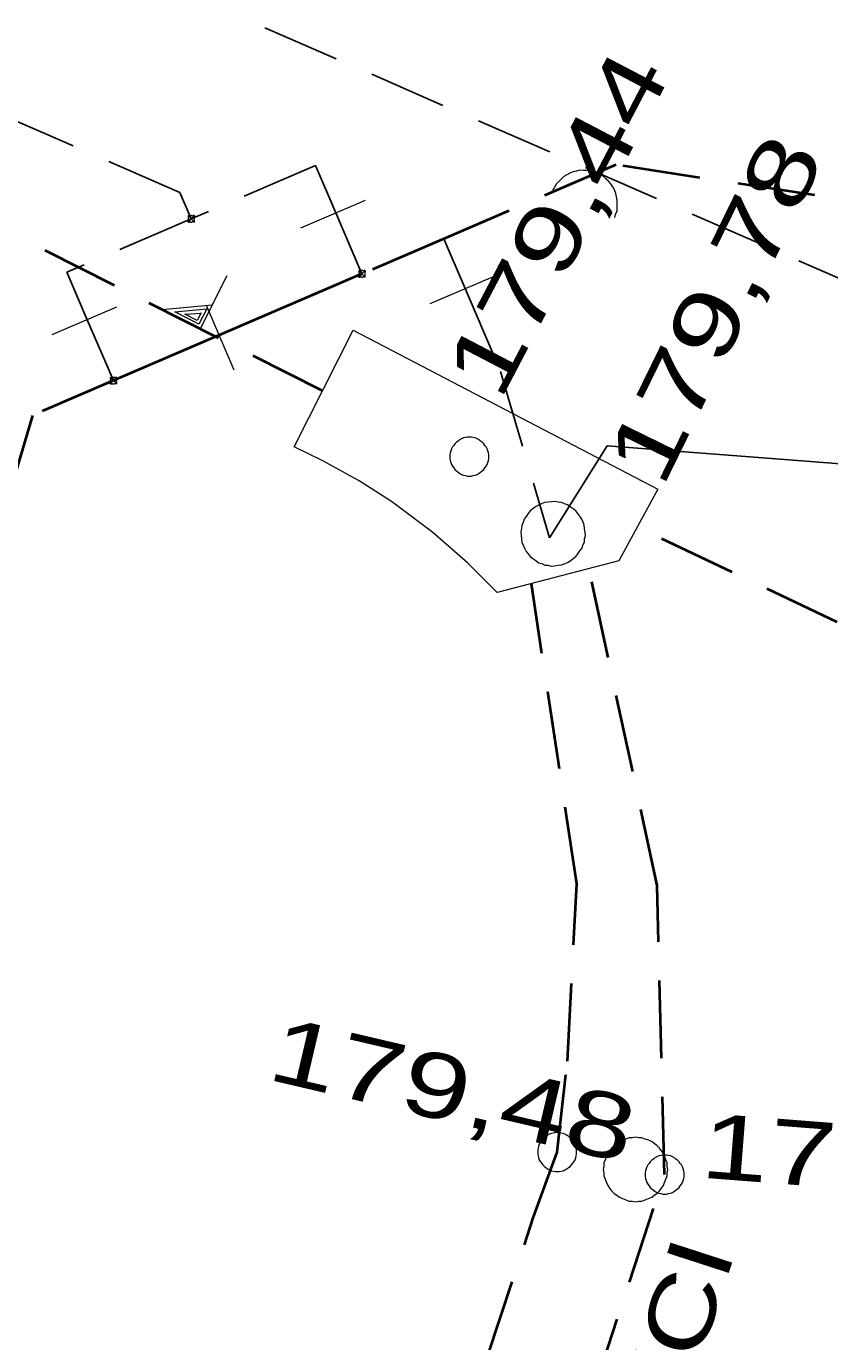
# Model space of a CAD drawing. Extents: x -740851 to -738888, y -1041382 to -1040235.
# Drawn here: x -739019.6 to -739007.19, y -1041347.67 to -1041327.35 of the extents above; entities that cross this region are included whole.
import ezdxf

# ---------------------------------------------------------------- set-up
doc = ezdxf.new("R2010")
doc.units = 0
doc.header["$LTSCALE"] = 0.4
doc.linetypes.add('MEDIUM_DASHED', pattern=[4.5, 3, -1.5])
doc.layers.add('18', color=7, linetype='Continuous', lineweight=13)
doc.layers.add('8', color=7, linetype='Continuous', lineweight=13)

msp = doc.modelspace()

# ---------------------------------------------------------------- linework, layer by layer
at = {"layer": '18', "linetype": 'MEDIUM_DASHED', "lineweight": 40}
msp.add_line((-739014.211, -1041358.725), (-739009.74, -1041345.09), dxfattribs=at)
for points in [[(-739015.025, -1041332.979), (-739045.2, -1041317.71), (-739098.28, -1041294.28)], [(-738957.54, -1041347.45), (-738989.227, -1041342.273), (-738994.634, -1041341.058), (-739000.628, -1041339.172), (-739005.448, -1041337.328), (-739010.163, -1041335.083)], [(-739009.74, -1041345.09), (-739009.855, -1041340.621), (-739010.909, -1041335.728)], [(-739011.4, -1041344.741), (-739011.241, -1041343.336), (-739011.097, -1041340.599), (-739011.799, -1041335.96)], [(-739015.852, -1041358.143), (-739011.77, -1041345.76), (-739011.4, -1041344.741)]]:
    msp.add_lwpolyline(points, dxfattribs=at)
at = {"layer": '18'}
for points in [[(-739016.501, -1041331.2), (-739016.916, -1041332.02), (-739017.501, -1041331.724), (-739016.729, -1041331.65)], [(-739016.813, -1041331.71), (-739016.934, -1041331.949), (-739017.308, -1041331.76), (-739016.81, -1041331.712)], [(-739016.9, -1041331.775), (-739016.96, -1041331.894), (-739017.152, -1041331.797), (-739016.896, -1041331.777)]]:
    msp.add_lwpolyline(points, dxfattribs=at)
for points in [[(-739009.847, -1041334.498), (-739010.447, -1041335.608), (-739012.327, -1041336.098), (-739012.781, -1041335.64), (-739013.321, -1041335.166), (-739013.959, -1041334.69), (-739014.46, -1041334.369), (-739015.019, -1041334.059), (-739015.463, -1041333.845), (-739014.551, -1041332.041)], [(-739012.457, -1041333.996), (-739012.457, -1041333.966), (-739012.463, -1041333.936), (-739012.469, -1041333.906), (-739012.481, -1041333.876), (-739012.499, -1041333.846), (-739012.517, -1041333.822), (-739012.535, -1041333.798), (-739012.559, -1041333.774), (-739012.583, -1041333.756), (-739012.607, -1041333.738), (-739012.637, -1041333.72), (-739012.667, -1041333.708), (-739012.697, -1041333.702), (-739012.727, -1041333.696), (-739012.757, -1041333.696), (-739012.787, -1041333.696), (-739012.817, -1041333.702), (-739012.847, -1041333.708), (-739012.877, -1041333.72), (-739012.907, -1041333.738), (-739012.931, -1041333.756), (-739012.955, -1041333.774), (-739012.979, -1041333.798), (-739012.997, -1041333.822), (-739013.015, -1041333.846), (-739013.033, -1041333.876), (-739013.045, -1041333.906), (-739013.051, -1041333.936), (-739013.057, -1041333.966), (-739013.057, -1041333.996), (-739013.057, -1041334.026), (-739013.051, -1041334.056), (-739013.045, -1041334.086), (-739013.033, -1041334.116), (-739013.015, -1041334.146), (-739012.997, -1041334.17), (-739012.979, -1041334.194), (-739012.955, -1041334.218), (-739012.931, -1041334.236), (-739012.907, -1041334.254), (-739012.877, -1041334.272), (-739012.847, -1041334.284), (-739012.817, -1041334.29), (-739012.787, -1041334.296), (-739012.757, -1041334.296), (-739012.727, -1041334.296), (-739012.697, -1041334.29), (-739012.667, -1041334.284), (-739012.637, -1041334.272), (-739012.607, -1041334.254), (-739012.583, -1041334.236), (-739012.559, -1041334.218), (-739012.535, -1041334.194), (-739012.517, -1041334.17), (-739012.499, -1041334.146), (-739012.481, -1041334.116), (-739012.469, -1041334.086), (-739012.463, -1041334.056), (-739012.457, -1041334.026)], [(-739010.98, -1041335.317), (-739010.977, -1041335.266), (-739010.964, -1041335.218), (-739010.97, -1041335.164), (-739010.976, -1041335.111), (-739010.983, -1041335.057), (-739011.001, -1041335.011), (-739011.02, -1041334.964), (-739011.048, -1041334.915), (-739011.079, -1041334.876), (-739011.11, -1041334.836), (-739011.153, -1041334.804), (-739011.197, -1041334.772), (-739011.24, -1041334.739), (-739011.288, -1041334.726), (-739011.334, -1041334.704), (-739011.385, -1041334.7), (-739011.433, -1041334.687), (-739011.487, -1041334.694), (-739011.54, -1041334.7), (-739011.594, -1041334.707), (-739011.64, -1041334.725), (-739011.687, -1041334.744), (-739011.736, -1041334.772), (-739011.775, -1041334.803), (-739011.815, -1041334.834), (-739011.847, -1041334.877), (-739011.879, -1041334.92), (-739011.912, -1041334.964), (-739011.925, -1041335.012), (-739011.947, -1041335.058), (-739011.951, -1041335.109), (-739011.964, -1041335.157), (-739011.957, -1041335.211), (-739011.951, -1041335.264), (-739011.944, -1041335.318), (-739011.926, -1041335.364), (-739011.907, -1041335.411), (-739011.879, -1041335.46), (-739011.848, -1041335.499), (-739011.817, -1041335.539), (-739011.774, -1041335.571), (-739011.731, -1041335.603), (-739011.687, -1041335.636), (-739011.639, -1041335.649), (-739011.593, -1041335.671), (-739011.542, -1041335.674), (-739011.494, -1041335.687), (-739011.44, -1041335.681), (-739011.387, -1041335.675), (-739011.333, -1041335.668), (-739011.287, -1041335.65), (-739011.24, -1041335.631), (-739011.191, -1041335.603), (-739011.152, -1041335.572), (-739011.112, -1041335.541), (-739011.08, -1041335.498), (-739011.048, -1041335.454), (-739011.015, -1041335.411), (-739011.002, -1041335.363)], [(-739011.1, -1041344.741), (-739011.1, -1041344.711), (-739011.106, -1041344.681), (-739011.112, -1041344.651), (-739011.124, -1041344.621), (-739011.142, -1041344.591), (-739011.16, -1041344.567), (-739011.178, -1041344.543), (-739011.202, -1041344.519), (-739011.226, -1041344.501), (-739011.25, -1041344.483), (-739011.28, -1041344.465), (-739011.31, -1041344.453), (-739011.34, -1041344.447), (-739011.37, -1041344.441), (-739011.4, -1041344.441), (-739011.43, -1041344.441), (-739011.46, -1041344.447), (-739011.49, -1041344.453), (-739011.52, -1041344.465), (-739011.55, -1041344.483), (-739011.574, -1041344.501), (-739011.598, -1041344.519), (-739011.622, -1041344.543), (-739011.64, -1041344.567), (-739011.658, -1041344.591), (-739011.676, -1041344.621), (-739011.688, -1041344.651), (-739011.694, -1041344.681), (-739011.7, -1041344.711), (-739011.7, -1041344.741), (-739011.7, -1041344.771), (-739011.694, -1041344.801), (-739011.688, -1041344.831), (-739011.676, -1041344.861), (-739011.658, -1041344.891), (-739011.64, -1041344.915), (-739011.622, -1041344.939), (-739011.598, -1041344.963), (-739011.574, -1041344.981), (-739011.55, -1041344.999), (-739011.52, -1041345.017), (-739011.49, -1041345.029), (-739011.46, -1041345.035), (-739011.43, -1041345.041), (-739011.4, -1041345.041), (-739011.37, -1041345.041), (-739011.34, -1041345.035), (-739011.31, -1041345.029), (-739011.28, -1041345.017), (-739011.25, -1041344.999), (-739011.226, -1041344.981), (-739011.202, -1041344.963), (-739011.178, -1041344.939), (-739011.16, -1041344.915), (-739011.142, -1041344.891), (-739011.124, -1041344.861), (-739011.112, -1041344.831), (-739011.106, -1041344.801), (-739011.1, -1041344.771)], [(-739009.69, -1041345.01), (-739009.7, -1041344.96), (-739009.7, -1041344.91), (-739009.72, -1041344.86), (-739009.74, -1041344.81), (-739009.76, -1041344.76), (-739009.79, -1041344.72), (-739009.82, -1041344.68), (-739009.86, -1041344.64), (-739009.9, -1041344.61), (-739009.94, -1041344.58), (-739009.99, -1041344.56), (-739010.04, -1041344.54), (-739010.09, -1041344.52), (-739010.14, -1041344.52), (-739010.19, -1041344.51), (-739010.24, -1041344.52), (-739010.29, -1041344.52), (-739010.34, -1041344.54), (-739010.39, -1041344.56), (-739010.44, -1041344.58), (-739010.48, -1041344.61), (-739010.52, -1041344.64), (-739010.56, -1041344.68), (-739010.59, -1041344.72), (-739010.62, -1041344.76), (-739010.64, -1041344.81), (-739010.66, -1041344.86), (-739010.68, -1041344.91), (-739010.68, -1041344.96), (-739010.69, -1041345.01), (-739010.68, -1041345.06), (-739010.68, -1041345.11), (-739010.66, -1041345.16), (-739010.64, -1041345.21), (-739010.62, -1041345.26), (-739010.59, -1041345.3), (-739010.56, -1041345.34), (-739010.52, -1041345.38), (-739010.48, -1041345.41), (-739010.44, -1041345.44), (-739010.39, -1041345.46), (-739010.34, -1041345.48), (-739010.29, -1041345.5), (-739010.24, -1041345.5), (-739010.19, -1041345.51), (-739010.14, -1041345.5), (-739010.09, -1041345.5), (-739010.04, -1041345.48), (-739009.99, -1041345.46), (-739009.94, -1041345.44), (-739009.9, -1041345.41), (-739009.86, -1041345.38), (-739009.82, -1041345.34), (-739009.79, -1041345.3), (-739009.76, -1041345.26), (-739009.74, -1041345.21), (-739009.72, -1041345.16), (-739009.7, -1041345.11), (-739009.7, -1041345.06)], [(-739009.44, -1041345.09), (-739009.44, -1041345.06), (-739009.446, -1041345.03), (-739009.452, -1041345), (-739009.464, -1041344.97), (-739009.482, -1041344.94), (-739009.5, -1041344.916), (-739009.518, -1041344.892), (-739009.542, -1041344.868), (-739009.566, -1041344.85), (-739009.59, -1041344.832), (-739009.62, -1041344.814), (-739009.65, -1041344.802), (-739009.68, -1041344.796), (-739009.71, -1041344.79), (-739009.74, -1041344.79), (-739009.77, -1041344.79), (-739009.8, -1041344.796), (-739009.83, -1041344.802), (-739009.86, -1041344.814), (-739009.89, -1041344.832), (-739009.914, -1041344.85), (-739009.938, -1041344.868), (-739009.962, -1041344.892), (-739009.98, -1041344.916), (-739009.998, -1041344.94), (-739010.016, -1041344.97), (-739010.028, -1041345), (-739010.034, -1041345.03), (-739010.04, -1041345.06), (-739010.04, -1041345.09), (-739010.04, -1041345.12), (-739010.034, -1041345.15), (-739010.028, -1041345.18), (-739010.016, -1041345.21), (-739009.998, -1041345.24), (-739009.98, -1041345.264), (-739009.962, -1041345.288), (-739009.938, -1041345.312), (-739009.914, -1041345.33), (-739009.89, -1041345.348), (-739009.86, -1041345.366), (-739009.83, -1041345.378), (-739009.8, -1041345.384), (-739009.77, -1041345.39), (-739009.74, -1041345.39), (-739009.71, -1041345.39), (-739009.68, -1041345.384), (-739009.65, -1041345.378), (-739009.62, -1041345.366), (-739009.59, -1041345.348), (-739009.566, -1041345.33), (-739009.542, -1041345.312), (-739009.518, -1041345.288), (-739009.5, -1041345.264), (-739009.482, -1041345.24), (-739009.464, -1041345.21), (-739009.452, -1041345.18), (-739009.446, -1041345.15), (-739009.44, -1041345.12)]]:
    msp.add_lwpolyline(points, close=True, dxfattribs=at)
at = {"layer": '8'}
for p, q in [((-739015.36, -1041330.462), (-739014.36, -1041330.032)), ((-739017.101, -1041330.372), (-739017.001, -1041330.272)), ((-739017.101, -1041330.272), (-739017.001, -1041330.372)), ((-739017.101, -1041330.272), (-739017.101, -1041330.292)), ((-739017.101, -1041330.272), (-739017.081, -1041330.272)), ((-739017.001, -1041330.272), (-739017.021, -1041330.272)), ((-739017.001, -1041330.272), (-739017.001, -1041330.292)), ((-739017.101, -1041330.372), (-739017.101, -1041330.352)), ((-739017.101, -1041330.372), (-739017.081, -1041330.372)), ((-739017.001, -1041330.372), (-739017.021, -1041330.372)), ((-739017.001, -1041330.372), (-739017.001, -1041330.352)), ((-739014.464, -1041331.221), (-739014.364, -1041331.121)), ((-739014.464, -1041331.121), (-739014.364, -1041331.221)), ((-739014.464, -1041331.121), (-739014.464, -1041331.141)), ((-739014.464, -1041331.121), (-739014.444, -1041331.121)), ((-739014.364, -1041331.121), (-739014.384, -1041331.121)), ((-739014.364, -1041331.121), (-739014.364, -1041331.141)), ((-739014.464, -1041331.221), (-739014.464, -1041331.201)), ((-739014.464, -1041331.221), (-739014.444, -1041331.221)), ((-739014.364, -1041331.221), (-739014.384, -1041331.221)), ((-739014.364, -1041331.221), (-739014.364, -1041331.201)), ((-739013.36, -1041331.63), (-739012.36, -1041331.204)), ((-739019.2, -1041332.11), (-739018.2, -1041331.684)), ((-739016.388, -1041332.66), (-739016.818, -1041331.66)), ((-739018.304, -1041332.871), (-739018.204, -1041332.771)), ((-739018.304, -1041332.771), (-739018.204, -1041332.871)), ((-739018.304, -1041332.771), (-739018.304, -1041332.791)), ((-739018.304, -1041332.771), (-739018.284, -1041332.771)), ((-739018.204, -1041332.771), (-739018.224, -1041332.771)), ((-739018.204, -1041332.771), (-739018.204, -1041332.791)), ((-739018.304, -1041332.871), (-739018.304, -1041332.851)), ((-739018.304, -1041332.871), (-739018.284, -1041332.871)), ((-739018.204, -1041332.871), (-739018.224, -1041332.871)), ((-739018.204, -1041332.871), (-739018.204, -1041332.851))]:
    msp.add_line(p, q, dxfattribs=at)
at = {"layer": '8', "lineweight": 25}
for p, q in [((-739014.415, -1041331.172), (-739014.82, -1041330.23)), ((-739013.151, -1041330.629), (-739012.82, -1041331.4)), ((-739018.66, -1041331.88), (-739018.255, -1041332.822))]:
    msp.add_line(p, q, dxfattribs=at)
at = {"layer": '8', "lineweight": 40}
for p, q in [((-739014.415, -1041331.172), (-739016.62, -1041332.12)), ((-739016.62, -1041332.12), (-739018.255, -1041332.822))]:
    msp.add_line(p, q, dxfattribs=at)
at = {"layer": '8', "linetype": 'MEDIUM_DASHED', "lineweight": 40}
for points in [[(-739035.327, -1040869.176), (-739031.896, -1040886.019), (-739019.793, -1040911.158), (-738971.377, -1041006.096), (-738926.048, -1041090.986), (-738916.972, -1041110.384), (-738894.08, -1041157.618), (-738888.006, -1041177.327), (-738893.192, -1041219.807), (-738897.568, -1041245.006), (-738897.033, -1041287.959), (-738895.284, -1041302.914), (-738892.075, -1041339.057), (-738904.789, -1041346.08), (-738934.47, -1041341.14), (-739010.494, -1041329.487), (-739013.151, -1041330.629), (-739014.415, -1041331.172)], [(-739018.255, -1041332.822), (-739019.505, -1041333.359), (-739022.37, -1041343.05), (-739027.082, -1041357.662)]]:
    msp.add_lwpolyline(points, dxfattribs=at)
at = {"layer": '8', "linetype": 'MEDIUM_DASHED', "lineweight": 25}
for points in [[(-738998.96, -1041334.03), (-739001.617, -1041333.611), (-739026.435, -1041322.774)], [(-739017.052, -1041330.323), (-739017.227, -1041329.915), (-739021.15, -1041328.205)], [(-739014.82, -1041330.23), (-739015.132, -1041329.498), (-739017.052, -1041330.323)], [(-739017.052, -1041330.323), (-739018.972, -1041331.148), (-739018.66, -1041331.88)], [(-739012.82, -1041331.4), (-739012.274, -1041332.681), (-739011.52, -1041335.25)]]:
    msp.add_lwpolyline(points, dxfattribs=at)
at = {"layer": '8'}
msp.add_lwpolyline([(-739010.509, -1041330.301), (-739010.497, -1041330.249), (-739010.476, -1041330.201), (-739010.474, -1041330.144), (-739010.473, -1041330.088), (-739010.471, -1041330.031), (-739010.483, -1041329.98), (-739010.495, -1041329.929), (-739010.517, -1041329.874), (-739010.543, -1041329.828), (-739010.569, -1041329.782), (-739010.608, -1041329.742), (-739010.648, -1041329.702), (-739010.688, -1041329.662), (-739010.736, -1041329.641), (-739010.78, -1041329.61), (-739010.832, -1041329.599), (-739010.88, -1041329.578), (-739010.937, -1041329.576), (-739010.993, -1041329.574), (-739011.05, -1041329.572), (-739011.101, -1041329.584), (-739011.152, -1041329.596), (-739011.207, -1041329.618), (-739011.253, -1041329.644), (-739011.299, -1041329.67), (-739011.339, -1041329.71), (-739011.379, -1041329.749), (-739011.419, -1041329.789), (-739011.44, -1041329.837), (-739011.471, -1041329.881)], dxfattribs=at)
for points in [[(-739017.001, -1041330.322), (-739017.001, -1041330.317), (-739017.002, -1041330.312), (-739017.003, -1041330.307), (-739017.005, -1041330.302), (-739017.008, -1041330.297), (-739017.011, -1041330.293), (-739017.014, -1041330.289), (-739017.018, -1041330.285), (-739017.022, -1041330.282), (-739017.026, -1041330.279), (-739017.031, -1041330.276), (-739017.036, -1041330.274), (-739017.041, -1041330.273), (-739017.046, -1041330.272), (-739017.051, -1041330.272), (-739017.056, -1041330.272), (-739017.061, -1041330.273), (-739017.066, -1041330.274), (-739017.071, -1041330.276), (-739017.076, -1041330.279), (-739017.08, -1041330.282), (-739017.084, -1041330.285), (-739017.088, -1041330.289), (-739017.091, -1041330.293), (-739017.094, -1041330.297), (-739017.097, -1041330.302), (-739017.099, -1041330.307), (-739017.1, -1041330.312), (-739017.101, -1041330.317), (-739017.101, -1041330.322), (-739017.101, -1041330.327), (-739017.1, -1041330.332), (-739017.099, -1041330.337), (-739017.097, -1041330.342), (-739017.094, -1041330.347), (-739017.091, -1041330.351), (-739017.088, -1041330.355), (-739017.084, -1041330.359), (-739017.08, -1041330.362), (-739017.076, -1041330.365), (-739017.071, -1041330.368), (-739017.066, -1041330.37), (-739017.061, -1041330.371), (-739017.056, -1041330.372), (-739017.051, -1041330.372), (-739017.046, -1041330.372), (-739017.041, -1041330.371), (-739017.036, -1041330.37), (-739017.031, -1041330.368), (-739017.026, -1041330.365), (-739017.022, -1041330.362), (-739017.018, -1041330.359), (-739017.014, -1041330.355), (-739017.011, -1041330.351), (-739017.008, -1041330.347), (-739017.005, -1041330.342), (-739017.003, -1041330.337), (-739017.002, -1041330.332), (-739017.001, -1041330.327)], [(-739014.364, -1041331.171), (-739014.364, -1041331.166), (-739014.365, -1041331.161), (-739014.366, -1041331.156), (-739014.368, -1041331.151), (-739014.371, -1041331.146), (-739014.374, -1041331.142), (-739014.377, -1041331.138), (-739014.381, -1041331.134), (-739014.385, -1041331.131), (-739014.389, -1041331.128), (-739014.394, -1041331.125), (-739014.399, -1041331.123), (-739014.404, -1041331.122), (-739014.409, -1041331.121), (-739014.414, -1041331.121), (-739014.419, -1041331.121), (-739014.424, -1041331.122), (-739014.429, -1041331.123), (-739014.434, -1041331.125), (-739014.439, -1041331.128), (-739014.443, -1041331.131), (-739014.447, -1041331.134), (-739014.451, -1041331.138), (-739014.454, -1041331.142), (-739014.457, -1041331.146), (-739014.46, -1041331.151), (-739014.462, -1041331.156), (-739014.463, -1041331.161), (-739014.464, -1041331.166), (-739014.464, -1041331.171), (-739014.464, -1041331.176), (-739014.463, -1041331.181), (-739014.462, -1041331.186), (-739014.46, -1041331.191), (-739014.457, -1041331.196), (-739014.454, -1041331.2), (-739014.451, -1041331.204), (-739014.447, -1041331.208), (-739014.443, -1041331.211), (-739014.439, -1041331.214), (-739014.434, -1041331.217), (-739014.429, -1041331.219), (-739014.424, -1041331.22), (-739014.419, -1041331.221), (-739014.414, -1041331.221), (-739014.409, -1041331.221), (-739014.404, -1041331.22), (-739014.399, -1041331.219), (-739014.394, -1041331.217), (-739014.389, -1041331.214), (-739014.385, -1041331.211), (-739014.381, -1041331.208), (-739014.377, -1041331.204), (-739014.374, -1041331.2), (-739014.371, -1041331.196), (-739014.368, -1041331.191), (-739014.366, -1041331.186), (-739014.365, -1041331.181), (-739014.364, -1041331.176)], [(-739018.204, -1041332.821), (-739018.204, -1041332.816), (-739018.205, -1041332.811), (-739018.206, -1041332.806), (-739018.208, -1041332.801), (-739018.211, -1041332.796), (-739018.214, -1041332.792), (-739018.217, -1041332.788), (-739018.221, -1041332.784), (-739018.225, -1041332.781), (-739018.229, -1041332.778), (-739018.234, -1041332.775), (-739018.239, -1041332.773), (-739018.244, -1041332.772), (-739018.249, -1041332.771), (-739018.254, -1041332.771), (-739018.259, -1041332.771), (-739018.264, -1041332.772), (-739018.269, -1041332.773), (-739018.274, -1041332.775), (-739018.279, -1041332.778), (-739018.283, -1041332.781), (-739018.287, -1041332.784), (-739018.291, -1041332.788), (-739018.294, -1041332.792), (-739018.297, -1041332.796), (-739018.3, -1041332.801), (-739018.302, -1041332.806), (-739018.303, -1041332.811), (-739018.304, -1041332.816), (-739018.304, -1041332.821), (-739018.304, -1041332.826), (-739018.303, -1041332.831), (-739018.302, -1041332.836), (-739018.3, -1041332.841), (-739018.297, -1041332.846), (-739018.294, -1041332.85), (-739018.291, -1041332.854), (-739018.287, -1041332.858), (-739018.283, -1041332.861), (-739018.279, -1041332.864), (-739018.274, -1041332.867), (-739018.269, -1041332.869), (-739018.264, -1041332.87), (-739018.259, -1041332.871), (-739018.254, -1041332.871), (-739018.249, -1041332.871), (-739018.244, -1041332.87), (-739018.239, -1041332.869), (-739018.234, -1041332.867), (-739018.229, -1041332.864), (-739018.225, -1041332.861), (-739018.221, -1041332.858), (-739018.217, -1041332.854), (-739018.214, -1041332.85), (-739018.211, -1041332.846), (-739018.208, -1041332.841), (-739018.206, -1041332.836), (-739018.205, -1041332.831), (-739018.204, -1041332.826)]]:
    msp.add_lwpolyline(points, close=True, dxfattribs=at)
at = {"layer": '8', "lineweight": 25}
msp.add_lwpolyline([(-738998.05, -1041334.48), (-738998.14, -1041334.79), (-739010.63, -1041333.83), (-739011.52, -1041335.25)], dxfattribs=at)

# ---------------------------------------------------------------- texts
at = {"layer": '18'}
for s, rotation, width, p in [('179,44', 62.415, 1.4, (-739012.286, -1041333.157)), ('179,78', 63.902, 1.4, (-739009.778, -1041334.503)), ('179,48', 346.824, 1.4, (-739015.91, -1041343.611)), ('179,48', 355.55, 1.4, (-739009.206, -1041345.134)), ('A665/1330ZCI', 72.025, 1.35, (-739012.239, -1041357.364))]:
    msp.add_text(s, height=1, rotation=rotation, dxfattribs=dict(at, width=width)).set_placement(p)

doc.saveas('drawing.dxf')
